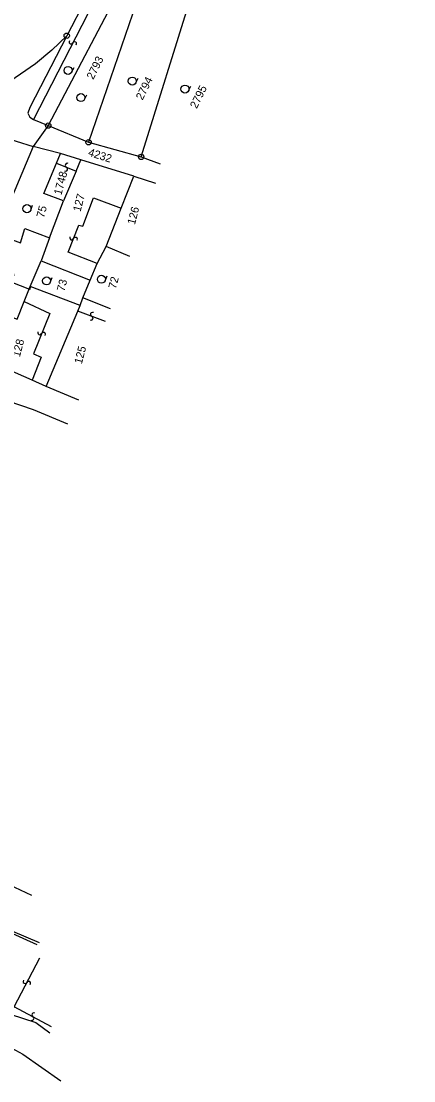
# Model space of a CAD drawing. Extents: x -658910 to -658078, y -1170373 to -1169331.
# Drawn here: x -658315 to -658241.4, y -1170114.5 to -1169916 of the extents above; entities that cross this region are included whole.
import ezdxf

# ---------------------------------------------------------------- set-up
doc = ezdxf.new("R2010")
doc.units = 0
doc.layers.add('Vrstva 8', color=7, linetype='Continuous')
doc.layers.add('Vrstva 9', color=7, linetype='Continuous')

msp = doc.modelspace()

# ---------------------------------------------------------------- linework, layer by layer
at = {"layer": 'Vrstva 8'}
for p, q in [((-658306.491, -1169918.719), (-658306.391, -1169918.719)), ((-658306.491, -1169918.719), (-658306.391, -1169918.719)), ((-658309.96, -1169935.57), (-658309.86, -1169935.57)), ((-658309.96, -1169935.57), (-658309.86, -1169935.57)), ((-658309.96, -1169935.57), (-658309.86, -1169935.57)), ((-658302.402, -1169938.691), (-658302.302, -1169938.691)), ((-658302.402, -1169938.691), (-658302.302, -1169938.691)), ((-658292.55, -1169941.42), (-658292.45, -1169941.42)), ((-658292.55, -1169941.42), (-658292.45, -1169941.42))]:
    msp.add_line(p, q, dxfattribs=at)
for points in [[(-658241.422, -1169797.309), (-658274.379, -1169859.65), (-658298.41, -1169905.359), (-658299.328, -1169904.949), (-658306.441, -1169918.719), (-658309.219, -1169921.43), (-658312.328, -1169924.01), (-658317.922, -1169927.83), (-658323.578, -1169930.32), (-658329.719, -1169932.26), (-658318.578, -1169935.711), (-658319.199, -1169937.449), (-658321.859, -1169936.67), (-658326.539, -1169935.43), (-658331.32, -1169933.879), (-658341.281, -1169937.379)], [(-658297.91, -1169905.719), (-658312.691, -1169934.43)], [(-658292.059, -1169908.65), (-658295.012, -1169907.121), (-658309.91, -1169935.57)], [(-658283.059, -1169911.109), (-658284.52, -1169910.59), (-658289.52, -1169909.059), (-658289.91, -1169909.92), (-658292.059, -1169908.65), (-658302.352, -1169938.691)], [(-658292.5, -1169941.42), (-658283.059, -1169911.109), (-658279.07, -1169912.35)], [(-658306.441, -1169918.719), (-658313.371, -1169932.18), (-658313.73, -1169933.219), (-658313.371, -1169933.949), (-658312.691, -1169934.43), (-658309.91, -1169935.57), (-658312.738, -1169939.5)], [(-658309.91, -1169935.57), (-658302.352, -1169938.691), (-658292.5, -1169941.42), (-658288.961, -1169942.699)], [(-658319.199, -1169937.449), (-658312.738, -1169939.5)], [(-658293.871, -1169945.059), (-658303.809, -1169941.98), (-658307.602, -1169940.809), (-658312.738, -1169939.5), (-658319.68, -1169955.85), (-658315.109, -1169957.531), (-658314.281, -1169954.85), (-658309.691, -1169956.6), (-658307.031, -1169949.66), (-658310.73, -1169948.26), (-658308.352, -1169942.6), (-658307.602, -1169940.809)], [(-658308.352, -1169942.6), (-658304.691, -1169944.09), (-658303.809, -1169941.98)], [(-658304.211, -1169987.02), (-658310.301, -1169984.43), (-658312.949, -1169983.23), (-658319.25, -1169980.49), (-658323.109, -1169978.93), (-658328.238, -1169976.76), (-658332.602, -1169974.84), (-658337.059, -1169972.879), (-658339.289, -1169971.42), (-658345.48, -1169968.67), (-658345.18, -1169967.77), (-658347.699, -1169966.51), (-658352.16, -1169964.82), (-658353.91, -1169964.08), (-658356.148, -1169963.211), (-658361.5, -1169960.359), (-658364, -1169958.9), (-658370.238, -1169954.9), (-658370.91, -1169953.039), (-658370.961, -1169950.98), (-658370.371, -1169949.07), (-658369.371, -1169947.32), (-658367.84, -1169945.77)], [(-658310.301, -1169984.43), (-658304.34, -1169970.309), (-658303.93, -1169969.24), (-658303.43, -1169967.83), (-658302.07, -1169964.51), (-658300.738, -1169961.391), (-658299.078, -1169958.23), (-658296.262, -1169951.039), (-658293.871, -1169945.059), (-658289.84, -1169946.32)], [(-658304.691, -1169944.09), (-658307.031, -1169949.66)], [(-658371.59, -1169946.93), (-658372.68, -1169949.871), (-658372.75, -1169952.789), (-658372.371, -1169954.98), (-658371.969, -1169956.309), (-658361.73, -1169963.859), (-658339.211, -1169977.82), (-658329.41, -1169983.051), (-658312.75, -1169988.77), (-658306.32, -1169991.449)], [(-658300.738, -1169961.391), (-658306.16, -1169959.27), (-658304.18, -1169954.199), (-658303.461, -1169954.43), (-658301.43, -1169949.121), (-658296.262, -1169951.039)], [(-658309.691, -1169956.6), (-658311.27, -1169960.91)], [(-658294.629, -1169960.08), (-658299.078, -1169958.23)], [(-658303.93, -1169969.24), (-658313.301, -1169965.68), (-658311.27, -1169960.91), (-658302.07, -1169964.51)], [(-658298.25, -1169969.859), (-658303.43, -1169967.83)], [(-658314.449, -1169968.5), (-658309.629, -1169970.76), (-658312.691, -1169978.289), (-658311.211, -1169978.93), (-658312.949, -1169983.23)], [(-658299.172, -1169972.23), (-658304.34, -1169970.309)], [(-658325.27, -1170050.609), (-658335.391, -1170044.09), (-658356.809, -1170033.711), (-658357.809, -1170068.961), (-658311.621, -1170088.621)], [(-658312, -1170089), (-658325.148, -1170083.109), (-658321.602, -1170075.75), (-658313.039, -1170079.73)], [(-658311.539, -1170091.51), (-658317.02, -1170102.02), (-658312.238, -1170103.58), (-658309.59, -1170105.5)], [(-658309.32, -1170104.359), (-658316.301, -1170100.629)], [(-658323.559, -1170105.76), (-658319.559, -1170106.891), (-658314.66, -1170109.539), (-658307.531, -1170114.5)]]:
    msp.add_lwpolyline(points, dxfattribs=at)
msp.add_lwpolyline([(-658313.301, -1169965.68), (-658313.359, -1169966.25), (-658316.879, -1169964.92), (-658316.309, -1169963.48), (-658318.09, -1169962.789), (-658319.238, -1169965.6), (-658317.84, -1169966.15), (-658319.641, -1169970.32), (-658315.762, -1169971.84), (-658314.449, -1169968.5)], close=True, dxfattribs=at)
for centre in [(-658306.441, -1169918.719), (-658306.441, -1169918.719), (-658309.91, -1169935.57), (-658309.91, -1169935.57), (-658309.91, -1169935.57), (-658302.352, -1169938.691), (-658302.352, -1169938.691), (-658292.5, -1169941.42), (-658292.5, -1169941.42)]:
    msp.add_circle(centre, 0.499, dxfattribs=at)
for centre, radius, start, end in [((-658305.633, -1169919.893), 0.376, 145.77863, 332.08977), ((-658304.966, -1169920.242), 0.377, 325.10259, 152.76581), ((-658306.661, -1169943.698), 0.377, 240.2434, 67.90661), ((-658306.374, -1169943.002), 0.376, 60.91944, 247.23058), ((-658305.52, -1169956.588), 0.376, 151.66486, 337.97599), ((-658304.821, -1169956.867), 0.377, 330.98882, 158.65203), ((-658301.892, -1169971.623), 0.377, 242.00719, 69.67041), ((-658301.627, -1169970.918), 0.376, 62.68323, 248.99437), ((-658311.507, -1169974.385), 0.376, 150.95811, 337.26925), ((-658310.81, -1169974.672), 0.377, 330.28207, 157.94529), ((-658314.253, -1170095.891), 0.376, 145.45818, 331.76931), ((-658313.588, -1170096.244), 0.377, 324.78214, 152.44535), ((-658312.986, -1170102.822), 0.377, 234.29673, 61.95994), ((-658312.628, -1170102.159), 0.376, 54.97277, 241.2839)]:
    msp.add_arc(centre, radius, start, end, dxfattribs=at)
at = {"layer": 'Vrstva 9'}
for p, q in [((-658305.538, -1169925.58), (-658305.08, -1169924.692)), ((-658293.501, -1169927.57), (-658293.043, -1169926.682)), ((-658303.119, -1169930.663), (-658302.661, -1169929.775)), ((-658283.628, -1169929.052), (-658283.17, -1169928.164)), ((-658313.196, -1169951.389), (-658312.839, -1169950.456)), ((-658299.264, -1169964.633), (-658298.876, -1169963.712)), ((-658309.528, -1169964.925), (-658309.151, -1169963.999))]:
    msp.add_line(p, q, dxfattribs=at)
for centre in [(-658306.205, -1169925.237), (-658294.168, -1169927.227), (-658284.295, -1169928.709), (-658303.786, -1169930.32), (-658313.897, -1169951.121), (-658310.223, -1169964.642), (-658299.956, -1169964.342)]:
    msp.add_circle(centre, 0.75, dxfattribs=at)

# ---------------------------------------------------------------- texts
for s, rotation, p in [('2793', 63.88515, (-658301.47, -1169927.047)), ('2794', 63.88515, (-658292.247, -1169930.9)), ('2795', 63.88515, (-658282.098, -1169932.487)), ('4232', 342.74862, (-658302.551, -1169941.191)), ('1748', 75.37005, (-658307.446, -1169948.679)), ('127', 75.37005, (-658303.874, -1169951.799)), ('75', 75.37005, (-658310.716, -1169952.935)), ('126', 75.37005, (-658293.686, -1169954.225)), ('72', 75.37005, (-658297.237, -1169966.238)), ('73', 75.37005, (-658306.894, -1169966.728)), ('128', 75.37005, (-658315.236, -1169979.015)), ('125', 75.37005, (-658303.63, -1169980.325))]:
    msp.add_text(s, height=1.5, rotation=rotation, dxfattribs=at).set_placement(p)

doc.saveas('drawing.dxf')
